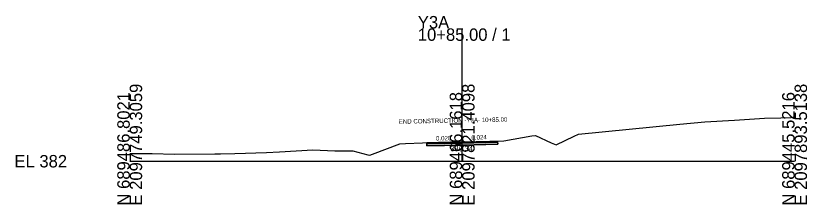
# Model space of a CAD drawing. Extents: x -26 to 2453, y -10 to 1032.
# Drawn here: x 2274.3 to 2452.8, y -9.7 to 32.8 of the extents above; entities that cross this region are included whole.
import ezdxf

# ---------------------------------------------------------------- set-up
doc = ezdxf.new("R2010")
doc.units = 0
for name, color, linetype in [('Exist Cross Section Cell', 7, 'Continuous'), ('Exist XS Center Line Elevation Label', 7, 'Continuous'), ('Exist XS Ground Line', 7, 'Continuous'), ('Prop CMT Pvmt Course 1', 7, 'Continuous'), ('Prop CMT Pvmt Course 2', 7, 'Continuous'), ('Prop CMT Pvmt Course 3', 7, 'Continuous'), ('Prop CMT Pvmt Surface', 7, 'Continuous'), ('Prop CMT Shld Paved Course 1', 7, 'Continuous'), ('Prop CMT Shld Paved Course 2', 7, 'Continuous'), ('Prop CMT Shld Paved Course 3', 7, 'Continuous'), ('Prop CMT Subgrade Earthwork', 7, 'Continuous'), ('Prop XS SE Text', 7, 'Continuous')]:
    doc.layers.add(name, color=color, linetype=linetype)

msp = doc.modelspace()

# ---------------------------------------------------------------- linework, layer by layer
at = {"layer": 'Exist Cross Section Cell'}
for p, q in [((2375, 0), (2375, 29.96)), ((2300, 0), (2375, 0)), ((2375, 0), (2450, 0))]:
    msp.add_line(p, q, dxfattribs=at)
at = {"layer": 'Exist XS Ground Line'}
msp.add_lwpolyline([(2300, 1.75), (2305.03, 1.76), (2310.09, 1.6), (2319.2, 1.68), (2320.49, 1.67), (2323.7, 1.74), (2330.89, 1.94), (2333.78, 2.14), (2341.3, 2.55), (2346.31, 2.34), (2350.32, 2.37), (2353.71, 1.45), (2354.15, 1.35), (2354.8, 1.58), (2360.96, 3.93), (2362.21, 4), (2366.09, 4.11), (2373.6, 4.31), (2375, 4.34), (2384.42, 4.56), (2390.73, 5.69), (2391.52, 5.81), (2395.1, 4.17), (2396.18, 3.68), (2400.3, 5.63), (2401.25, 6.08), (2424.1, 8.34), (2429.72, 8.89), (2436.48, 9.25), (2443.22, 9.68), (2446.9, 9.81), (2449.23, 9.89), (2450, 9.99)], dxfattribs=at)
at = {"layer": 'Prop CMT Pvmt Course 1'}
msp.add_line((2375, 4.34), (2383, 4.53), dxfattribs=at)
for points in [[(2375, 4.34), (2367, 4.18)], [(2367, 4.18), (2367, 3.93)], [(2367, 3.93), (2375, 4.09)], [(2375, 4.09), (2375, 4.34)], [(2375, 4.09), (2375, 4.34)], [(2375, 4.09), (2375, 4.34)], [(2383.01, 4.28), (2375.01, 4.09)], [(2383, 4.53), (2383.01, 4.28)]]:
    msp.add_lwpolyline(points, dxfattribs=at)
msp.add_lwpolyline([(2375, 4.09), (2375, 4.21), (2375, 4.21), (2375, 4.09)], close=True, dxfattribs=at)
msp.add_lwpolyline([(2375, 4.09), (2375, 4.21), (2375, 4.21), (2375, 4.09)], close=True, dxfattribs=at)
msp.add_lwpolyline([(2375, 4.09), (2375, 4.21), (2375, 4.21), (2375, 4.09)], close=True, dxfattribs=at)
msp.add_lwpolyline([(2375, 4.09), (2375, 4.21), (2375, 4.21), (2375, 4.09)], close=True, dxfattribs=at)
at = {"layer": 'Prop CMT Pvmt Course 2'}
for points in [[(2367, 3.93), (2375, 4.09)], [(2375, 4.09), (2367, 3.93)], [(2367, 3.93), (2367, 3.6)], [(2375, 3.76), (2375, 4.09)], [(2375, 3.76), (2375, 4.09)], [(2375, 3.76), (2375, 4.09)], [(2383.01, 4.28), (2375.01, 4.09)], [(2375.01, 4.09), (2383.01, 4.28)], [(2383.01, 4.28), (2383.02, 3.95)]]:
    msp.add_lwpolyline(points, dxfattribs=at)
at = {"layer": 'Prop CMT Pvmt Course 3'}
for points in [[(2375, 4.09), (2367, 3.93)], [(2367, 3.93), (2367, 3.47)], [(2367, 3.47), (2375, 3.63)], [(2375, 3.63), (2375, 4.09)], [(2375, 3.63), (2375, 4.09)], [(2375.01, 4.09), (2383.01, 4.28)], [(2383.03, 3.82), (2375.03, 3.63)], [(2383.01, 4.28), (2383.03, 3.82)]]:
    msp.add_lwpolyline(points, dxfattribs=at)
at = {"layer": 'Prop CMT Pvmt Surface'}
for points in [[(2375, 4.34), (2367, 4.18)], [(2375, 4.34), (2383, 4.53)]]:
    msp.add_lwpolyline(points, dxfattribs=at)
at = {"layer": 'Prop CMT Shld Paved Course 1'}
for points in [[(2367, 3.93), (2367, 4.18)], [(2383.01, 4.28), (2383, 4.53)]]:
    msp.add_lwpolyline(points, dxfattribs=at)
at = {"layer": 'Prop CMT Shld Paved Course 2'}
for points in [[(2367, 3.6), (2367, 3.93)], [(2383.02, 3.95), (2383.01, 4.28)]]:
    msp.add_lwpolyline(points, dxfattribs=at)
at = {"layer": 'Prop CMT Shld Paved Course 3'}
for points in [[(2367, 3.47), (2367, 3.93)], [(2383.03, 3.82), (2383.01, 4.28)]]:
    msp.add_lwpolyline(points, dxfattribs=at)
at = {"layer": 'Prop CMT Subgrade Earthwork'}
for points in [[(2367, 3.47), (2367, 4.18)], [(2375, 3.63), (2367, 3.47)], [(2375.03, 3.63), (2383.03, 3.82)]]:
    msp.add_lwpolyline(points, dxfattribs=at)

# ---------------------------------------------------------------- texts
at = {"layer": 'Exist Cross Section Cell'}
for s, p in [('Y3A', (2365, 29.96)), ('10+85.00 / 1', (2365, 27.16)), ('EL 382', (2274, -1.4))]:
    msp.add_text(s, height=2.8, dxfattribs=at).set_placement(p)
for s, p in [('E 2097749.3059', (2302.8, -10)), ('E 2097821.4098', (2377.8, -10)), ('E 2097893.5138', (2452.8, -10)), ('N 689486.8021', (2300, -10)), ('N 689466.1618', (2375, -10)), ('N 689445.5216', (2450, -10))]:
    msp.add_text(s, height=2.8, rotation=90, dxfattribs=at).set_placement(p)
at = {"layer": 'Exist XS Center Line Elevation Label'}
msp.add_text('386.34', height=1.2, dxfattribs=at).set_placement((2372.35, 2.24))
at = {"layer": 'Prop XS SE Text'}
for s, rotation, p in [('END CONSTRUCTION -Y3A- 10+85.00', 1.1458, (2360.71, 8.44)), ('0.020', 1.1458, (2369.11, 4.66)), ('0.024', 1.4734, (2377.11, 4.85))]:
    msp.add_text(s, height=1, rotation=rotation, dxfattribs=at).set_placement(p)

doc.saveas('drawing.dxf')
